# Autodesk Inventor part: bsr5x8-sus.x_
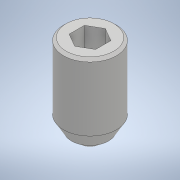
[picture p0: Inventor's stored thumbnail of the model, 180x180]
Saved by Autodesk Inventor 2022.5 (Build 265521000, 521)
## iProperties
Created: 2020-01
Part Number: bsr5x8-sus.x_
Material: 一般
Document SubType Name: Modeling
Designer: ImaoCorp
Density: 1 g/cm^3
Appearance: 既定
Sending System: SOLIDWORKS 2018-2018316
MC: AMD64
MC_MODEL: Intel64 Family 6 Model 60 Stepping 3, GenuineIntel
OS: Windows_NT
FRU: Parasolid Version 30.0, build 310,  6- 8-2018
FORMAT: text
GUISE: transmit
KEY: bsr5x8-sus
FILE: bsr5x8-sus.x_t
DATE: Thu Jan 23 16:47:14 2020
Author: ImaoCorp
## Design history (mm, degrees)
feature "Base1"
node "ソリッド1"
